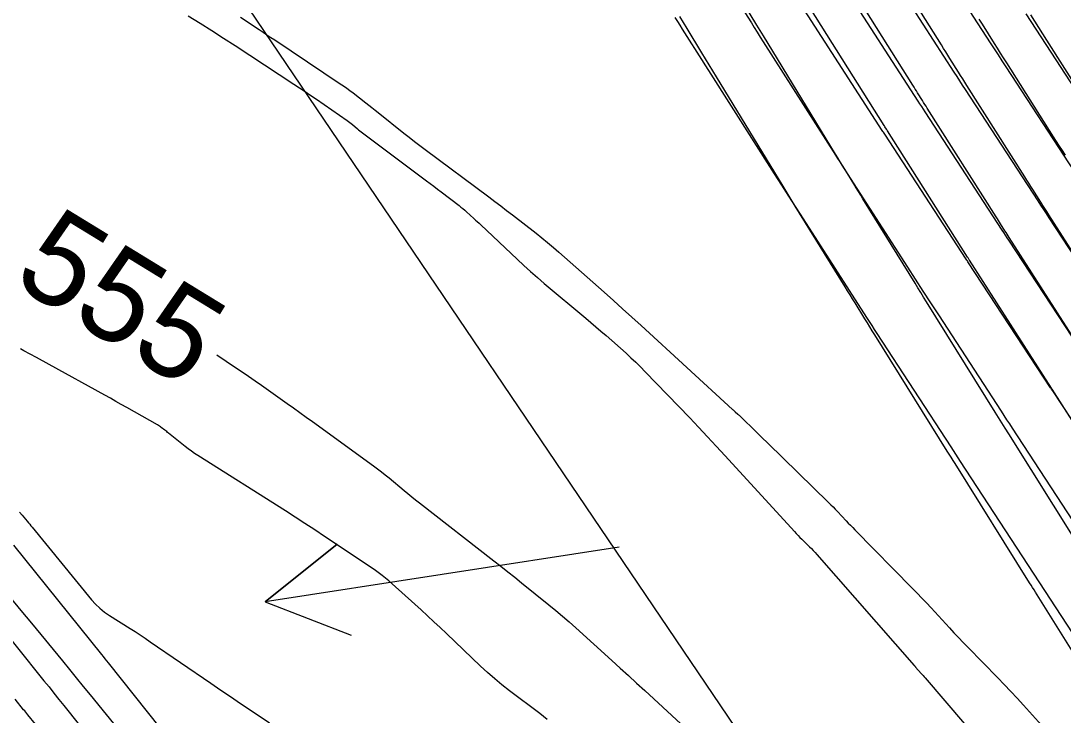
# Model space of a CAD drawing. Extents: x 954385 to 988206, y 1868364 to 1924553.
# Drawn here: x 957618.2 to 957686, y 1920108 to 1920153.2 of the extents above; entities that cross this region are included whole.
import ezdxf

# ---------------------------------------------------------------- set-up
doc = ezdxf.new("R2010")
doc.units = 0
for name, color, linetype in [('16', 7, 'Continuous'), ('26', 7, 'Continuous'), ('5', 7, 'Continuous'), ('6', 7, 'Continuous'), ('7', 7, 'Continuous'), ('Default', 7, 'Continuous')]:
    doc.layers.add(name, color=color, linetype=linetype)

msp = doc.modelspace()

# ---------------------------------------------------------------- linework, layer by layer
at = {"layer": '16'}
for points in [[(957676.664, 1920158.926), (957681.289, 1920151.772), (957681.542, 1920151.38), (957681.797, 1920150.988), (957682.051, 1920150.596), (957682.306, 1920150.205), (957686.746, 1920143.39)], [(957689.891, 1920133.126), (957685.137, 1920140.369), (957684.954, 1920140.648), (957684.771, 1920140.927), (957684.588, 1920141.206), (957684.406, 1920141.486), (957679.678, 1920148.744), (957679.495, 1920149.025), (957679.311, 1920149.307), (957679.129, 1920149.589), (957678.946, 1920149.871), (957674.227, 1920157.171)], [(957664.337, 1920155.283), (957665.737, 1920153.07), (957665.93, 1920152.764), (957666.123, 1920152.459), (957666.317, 1920152.154), (957666.511, 1920151.849), (957671.213, 1920144.464), (957671.354, 1920144.242), (957671.496, 1920144.02), (957671.638, 1920143.799), (957671.78, 1920143.577), (957675.911, 1920137.156), (957676.409, 1920136.382), (957676.909, 1920135.609), (957677.409, 1920134.836), (957677.911, 1920134.064), (957681.999, 1920127.774), (957682.178, 1920127.498), (957682.358, 1920127.222), (957682.538, 1920126.946), (957682.718, 1920126.67), (957717.191, 1920073.906)], [(957687.556, 1920131.218), (957682.506, 1920138.911), (957682.396, 1920139.078), (957682.286, 1920139.246), (957682.176, 1920139.414), (957682.067, 1920139.582), (957677.05, 1920147.282), (957676.938, 1920147.454), (957676.826, 1920147.626), (957676.715, 1920147.798), (957676.603, 1920147.97), (957671.624, 1920155.673)], [(957720.645, 1920075.559), (957685.358, 1920129.1), (957685.324, 1920129.152), (957685.289, 1920129.205), (957685.255, 1920129.257), (957685.22, 1920129.31), (957679.875, 1920137.452), (957679.838, 1920137.509), (957679.801, 1920137.565), (957679.764, 1920137.622), (957679.727, 1920137.678), (957674.422, 1920145.821), (957674.382, 1920145.883), (957674.341, 1920145.945), (957674.301, 1920146.007), (957674.261, 1920146.069), (957668.999, 1920154.208)], [(957629.068, 1920153.539), (957629.84, 1920153.06), (957630.608, 1920152.576), (957631.373, 1920152.086), (957632.134, 1920151.591), (957635.953, 1920149.09), (957636.322, 1920148.847), (957636.69, 1920148.601), (957637.056, 1920148.353), (957637.42, 1920148.102), (957639.426, 1920146.712), (957639.513, 1920146.651), (957639.597, 1920146.587), (957639.68, 1920146.522), (957639.762, 1920146.454), (957640.084, 1920146.179), (957640.165, 1920146.111), (957640.247, 1920146.044), (957640.33, 1920145.979), (957640.414, 1920145.915), (957644.591, 1920142.787), (957644.829, 1920142.609), (957645.067, 1920142.429), (957645.304, 1920142.249), (957645.54, 1920142.067), (957646.705, 1920141.171), (957646.829, 1920141.073), (957646.952, 1920140.973), (957647.072, 1920140.87), (957647.19, 1920140.765), (957647.658, 1920140.34), (957647.775, 1920140.233), (957647.891, 1920140.126), (957648.007, 1920140.018), (957648.122, 1920139.91), (957650.483, 1920137.683), (957650.918, 1920137.279), (957651.358, 1920136.882), (957651.804, 1920136.49), (957652.256, 1920136.105), (957654.955, 1920133.841), (957655.287, 1920133.56), (957655.617, 1920133.278), (957655.945, 1920132.993), (957656.272, 1920132.707), (957657.575, 1920131.556), (957657.897, 1920131.265), (957658.214, 1920130.968), (957658.524, 1920130.664), (957658.828, 1920130.354), (957661.721, 1920127.338), (957662.302, 1920126.729), (957662.879, 1920126.117), (957663.452, 1920125.501), (957664.021, 1920124.881), (957668.536, 1920119.936), (957668.655, 1920119.808), (957668.775, 1920119.682), (957668.897, 1920119.558), (957669.02, 1920119.435), (957669.518, 1920118.949), (957669.642, 1920118.826), (957669.763, 1920118.701), (957669.881, 1920118.574), (957669.997, 1920118.444), (957676.341, 1920111.214), (957676.348, 1920111.205), (957676.356, 1920111.197), (957676.364, 1920111.189), (957676.372, 1920111.18), (957676.403, 1920111.148), (957676.411, 1920111.14), (957676.419, 1920111.132), (957676.426, 1920111.123), (957676.434, 1920111.115), (957676.794, 1920110.699), (957676.856, 1920110.627), (957676.918, 1920110.555), (957676.981, 1920110.483), (957677.043, 1920110.41), (957687.555, 1920098.121)], [(957714.14, 1920071.263), (957679.353, 1920124.508), (957679.199, 1920124.744), (957679.045, 1920124.981), (957678.891, 1920125.218), (957678.737, 1920125.454), (957673.931, 1920132.847), (957673.763, 1920133.107), (957673.594, 1920133.367), (957673.426, 1920133.627), (957673.259, 1920133.888), (957669.121, 1920140.32), (957668.652, 1920141.05), (957668.184, 1920141.78), (957667.717, 1920142.511), (957667.25, 1920143.242), (957662.96, 1920149.981), (957662.885, 1920150.099), (957662.81, 1920150.218), (957662.735, 1920150.336), (957662.66, 1920150.455), (957661.26, 1920152.668), (957661.102, 1920152.919), (957660.944, 1920153.169), (957660.786, 1920153.42)], [(957689.085, 1920145.294), (957684.934, 1920151.666), (957684.608, 1920152.167), (957684.282, 1920152.669), (957683.956, 1920153.171), (957683.631, 1920153.673)], [(957652.448, 1920107.695), (957651.962, 1920108.077), (957649.987, 1920109.573), (957649.5, 1920109.953), (957649.023, 1920110.347), (957648.558, 1920110.755), (957648.104, 1920111.175), (957645.885, 1920113.293), (957645.475, 1920113.681), (957645.064, 1920114.067), (957644.65, 1920114.45), (957644.234, 1920114.83), (957642.564, 1920116.348), (957642.14, 1920116.719), (957641.703, 1920117.073), (957641.253, 1920117.411), (957640.79, 1920117.731), (957637.94, 1920119.628), (957637.307, 1920120.046), (957636.672, 1920120.461), (957636.035, 1920120.872), (957635.395, 1920121.28), (957629.699, 1920124.884), (957629.485, 1920125.024), (957629.275, 1920125.171), (957629.069, 1920125.323), (957628.867, 1920125.481), (957627.788, 1920126.355), (957627.729, 1920126.402), (957627.671, 1920126.449), (957627.612, 1920126.496), (957627.553, 1920126.542), (957627.316, 1920126.727), (957627.256, 1920126.772), (957627.195, 1920126.814), (957627.132, 1920126.855), (957627.067, 1920126.893), (957625.069, 1920128.022), (957624.714, 1920128.222), (957624.359, 1920128.421), (957624.003, 1920128.619), (957623.646, 1920128.816), (957620.011, 1920130.815), (957619.187, 1920131.268), (957618.363, 1920131.721), (957618.157, 1920131.834)], [(957617.694, 1920119.048), (957623.424, 1920111.927), (957623.534, 1920111.79), (957623.644, 1920111.652), (957623.754, 1920111.515), (957623.863, 1920111.378), (957629.789, 1920103.942)], [(957614.235, 1920116.987), (957619.679, 1920110.221), (957620.005, 1920109.816), (957620.33, 1920109.411), (957620.654, 1920109.005), (957620.979, 1920108.599), (957625.894, 1920102.431)]]:
    msp.add_lwpolyline(points, dxfattribs=at)
at = {"layer": '26'}
msp.add_lwpolyline([(957657.131, 1920118.928), (957634.087, 1920115.365), (957638.764, 1920119.124), (957634.087, 1920115.365), (957639.681, 1920113.194)], dxfattribs=at)
at = {"layer": '6'}
for points in [[(957686.862, 1920119.332), (957682.492, 1920126.316), (957682.273, 1920126.666), (957682.054, 1920127.016), (957681.835, 1920127.367), (957681.617, 1920127.717), (957677.135, 1920134.911), (957676.948, 1920135.211), (957676.763, 1920135.51), (957676.577, 1920135.81), (957676.392, 1920136.11), (957673.004, 1920141.612), (957672.855, 1920141.854), (957672.706, 1920142.096), (957672.557, 1920142.338), (957672.408, 1920142.58), (957671.812, 1920143.548), (957671.663, 1920143.79), (957671.515, 1920144.033), (957671.366, 1920144.275), (957671.218, 1920144.518), (957666.518, 1920152.226), (957666.41, 1920152.403), (957666.303, 1920152.58), (957666.195, 1920152.758), (957666.088, 1920152.935), (957661.759, 1920160.111)], [(957683.915, 1920153.591), (957684.173, 1920153.18), (957684.431, 1920152.77), (957684.69, 1920152.36), (957684.949, 1920151.95), (957687.288, 1920148.262)], [(957630.931, 1920131.45), (957632.157, 1920130.627), (957632.58, 1920130.341), (957633.001, 1920130.052), (957633.421, 1920129.761), (957633.84, 1920129.468), (957635.51, 1920128.291), (957635.927, 1920127.996), (957636.343, 1920127.699), (957636.758, 1920127.401), (957637.171, 1920127.101), (957641.143, 1920124.214), (957641.399, 1920124.024), (957641.652, 1920123.83), (957641.902, 1920123.632), (957642.149, 1920123.429), (957643.129, 1920122.611), (957643.375, 1920122.408), (957643.622, 1920122.207), (957643.872, 1920122.007), (957644.123, 1920121.81), (957648.978, 1920118.031), (957649.429, 1920117.678), (957649.879, 1920117.323), (957650.327, 1920116.966), (957650.773, 1920116.607), (957652.556, 1920115.167), (957652.999, 1920114.803), (957653.437, 1920114.434), (957653.869, 1920114.058), (957654.297, 1920113.676), (957656.66, 1920111.534), (957657.194, 1920111.048), (957657.728, 1920110.561), (957658.261, 1920110.072), (957658.793, 1920109.583), (957663.778, 1920104.987)]]:
    msp.add_lwpolyline(points, dxfattribs=at)
at = {"layer": '7'}
for points in [[(957689.009, 1920134.478), (957685.115, 1920140.572), (957684.984, 1920140.778), (957684.853, 1920140.983), (957684.723, 1920141.189), (957684.593, 1920141.394), (957684.073, 1920142.218), (957683.943, 1920142.424), (957683.813, 1920142.629), (957683.682, 1920142.835), (957683.552, 1920143.041), (957679.777, 1920148.995), (957679.638, 1920149.214), (957679.499, 1920149.434), (957679.361, 1920149.654), (957679.222, 1920149.874), (957678.67, 1920150.754), (957678.532, 1920150.974), (957678.394, 1920151.194), (957678.256, 1920151.414), (957678.118, 1920151.634), (957674.468, 1920157.434)], [(957687.14, 1920131.879), (957682.53, 1920139.093), (957682.46, 1920139.205), (957682.389, 1920139.316), (957682.318, 1920139.427), (957682.248, 1920139.539), (957681.966, 1920139.985), (957681.896, 1920140.096), (957681.825, 1920140.207), (957681.755, 1920140.319), (957681.684, 1920140.43), (957677.19, 1920147.517), (957677.112, 1920147.642), (957677.033, 1920147.766), (957676.955, 1920147.891), (957676.876, 1920148.015), (957676.564, 1920148.514), (957676.485, 1920148.639), (957676.407, 1920148.763), (957676.329, 1920148.888), (957676.25, 1920149.013), (957671.88, 1920155.958)], [(957688.086, 1920124.893), (957685.317, 1920129.207), (957685.302, 1920129.231), (957685.27, 1920129.281), (957679.946, 1920137.615), (957679.924, 1920137.649), (957679.902, 1920137.683), (957679.849, 1920137.768), (957679.816, 1920137.82), (957674.604, 1920146.04), (957674.586, 1920146.069), (957674.567, 1920146.098), (957674.549, 1920146.127), (957674.53, 1920146.157), (957674.438, 1920146.303), (957674.402, 1920146.362), (957674.383, 1920146.391), (957669.293, 1920154.481)], [(957632.479, 1920153.444), (957633.692, 1920152.634), (957633.944, 1920152.466), (957634.196, 1920152.298), (957634.448, 1920152.129), (957634.701, 1920151.961), (957638.963, 1920149.111), (957639.177, 1920148.965), (957639.388, 1920148.816), (957639.597, 1920148.664), (957639.803, 1920148.508), (957640.624, 1920147.877), (957640.829, 1920147.719), (957641.033, 1920147.559), (957641.236, 1920147.399), (957641.438, 1920147.238), (957643.104, 1920145.901), (957643.45, 1920145.626), (957643.799, 1920145.354), (957644.15, 1920145.085), (957644.503, 1920144.819), (957648.638, 1920141.739), (957649.027, 1920141.448), (957649.414, 1920141.155), (957649.799, 1920140.86), (957650.183, 1920140.563), (957651.715, 1920139.37), (957652.096, 1920139.068), (957652.472, 1920138.762), (957652.843, 1920138.449), (957653.209, 1920138.13), (957656.142, 1920135.538), (957656.751, 1920134.998), (957657.357, 1920134.454), (957657.96, 1920133.908), (957658.561, 1920133.358), (957664.499, 1920127.899), (957664.542, 1920127.86), (957664.586, 1920127.82), (957664.63, 1920127.782), (957664.675, 1920127.743), (957664.853, 1920127.591), (957664.898, 1920127.552), (957664.941, 1920127.513), (957664.984, 1920127.473), (957665.027, 1920127.433), (957666.058, 1920126.426), (957666.429, 1920126.063), (957666.801, 1920125.7), (957670.763, 1920121.832), (957670.909, 1920121.687), (957671.055, 1920121.541), (957671.199, 1920121.393), (957671.341, 1920121.244), (957671.907, 1920120.644), (957672.049, 1920120.495), (957672.192, 1920120.346), (957672.335, 1920120.198), (957672.48, 1920120.051), (957676.234, 1920116.236), (957676.54, 1920115.922), (957676.844, 1920115.606), (957677.145, 1920115.287), (957677.443, 1920114.966), (957678.629, 1920113.674), (957678.927, 1920113.352), (957679.227, 1920113.033), (957679.53, 1920112.716), (957679.835, 1920112.401), (957681.778, 1920110.408), (957682.201, 1920109.969), (957682.621, 1920109.527), (957683.037, 1920109.08), (957683.448, 1920108.63), (957685.61, 1920106.243)], [(957688.693, 1920108.877), (957684.243, 1920115.982), (957684.146, 1920116.137), (957684.049, 1920116.292), (957683.951, 1920116.448), (957683.854, 1920116.603), (957678.997, 1920124.364), (957678.869, 1920124.57), (957678.741, 1920124.775), (957678.612, 1920124.981), (957678.484, 1920125.186), (957673.773, 1920132.749), (957673.611, 1920133.009), (957673.45, 1920133.269), (957673.289, 1920133.529), (957673.128, 1920133.79), (957672.486, 1920134.832), (957672.326, 1920135.093), (957672.165, 1920135.353), (957672.005, 1920135.614), (957671.845, 1920135.874), (957668.598, 1920141.146), (957668.4, 1920141.469), (957668.201, 1920141.792), (957668.004, 1920142.115), (957667.806, 1920142.439), (957663.468, 1920149.552), (957663.229, 1920149.946), (957662.99, 1920150.339), (957662.751, 1920150.733), (957662.513, 1920151.127), (957661.561, 1920152.705), (957661.324, 1920153.099), (957661.086, 1920153.493)], [(957686.18, 1920144.451), (957685.99, 1920144.751), (957685.8, 1920145.051), (957685.61, 1920145.351), (957685.42, 1920145.651), (957682.363, 1920150.472), (957682.164, 1920150.787), (957681.965, 1920151.102), (957681.767, 1920151.417), (957681.569, 1920151.733), (957680.777, 1920152.995), (957680.579, 1920153.31)], [(957618.091, 1920121.204), (957618.255, 1920121.007), (957618.583, 1920120.611), (957618.665, 1920120.512), (957618.747, 1920120.413), (957618.829, 1920120.314), (957618.91, 1920120.215), (957622.778, 1920115.502), (957623.039, 1920115.209), (957623.321, 1920114.94), (957623.623, 1920114.694), (957623.947, 1920114.472), (957625.283, 1920113.633), (957625.616, 1920113.421), (957625.946, 1920113.206), (957626.275, 1920112.988), (957626.601, 1920112.766), (957630.54, 1920110.063), (957630.968, 1920109.769), (957631.397, 1920109.477), (957631.826, 1920109.185), (957632.256, 1920108.894), (957634.364, 1920107.471)], [(957624.785, 1920106.747), (957622.703, 1920109.306), (957622.254, 1920109.857), (957621.804, 1920110.408), (957621.354, 1920110.959), (957620.903, 1920111.509), (957618.887, 1920113.965), (957618.196, 1920114.807), (957617.505, 1920115.648)], [(957619.118, 1920107.399), (957618.63, 1920107.998), (957618.561, 1920108.083), (957618.492, 1920108.168), (957618.423, 1920108.253), (957618.353, 1920108.337), (957617.798, 1920109.014)]]:
    msp.add_lwpolyline(points, dxfattribs=at)
at = {"layer": 'Default'}
msp.add_line((957696.959, 1920059.51), (957504.115, 1920344.606), dxfattribs=at)

# ---------------------------------------------------------------- texts
at = {"layer": '5'}
msp.add_text('555', height=6, rotation=328.51858, dxfattribs=at).set_placement((957617.486, 1920136.166))

doc.saveas('drawing.dxf')
